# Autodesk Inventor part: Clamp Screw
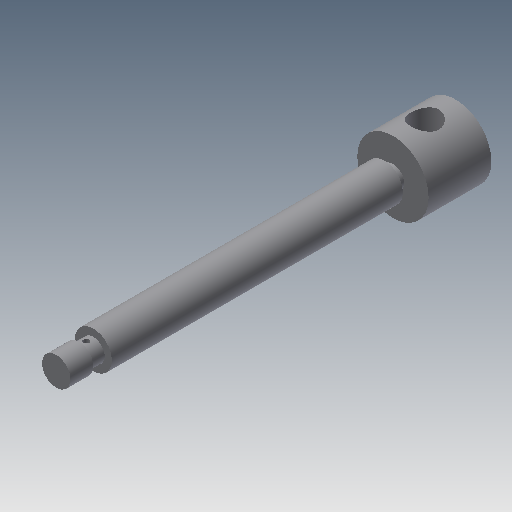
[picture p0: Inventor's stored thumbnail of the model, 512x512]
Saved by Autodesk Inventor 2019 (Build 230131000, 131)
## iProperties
Shininess: 77.0
Length Units: 11269
Angle Units: 11279
Time Units: 11290
Mass Units: 11283
Length Display Precision: 3
Angle Display Precision: 2
Created: 2002-02
Part Number: Clamp Screw
Document SubType Name: Modeling
Designer: ***
Density: 1 g/cm^3
Material: Generic
Mass: 23.4191 g
Surface Area: 81.8482 cm^2
Volume: 23.4191 cm^3
Appearance: Default
Density: 0.0
Volumn: 0.0
Area: 0.0
PropertySet Name: Model Information
Control State: 0
Master: False
Checked Out: False
Author: ***
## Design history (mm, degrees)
sketch "Sketch1"
  geometry: L1 (0, 140)-(5, 140); L2 (5, 140)-(5, 132); L3 (5, 132)-(4, 132); L4 (4, 132)-(4, 127); L5 (4, 127)-(6.5, 127); L6 (6.5, 127)-(6.5, 25); L7 (6.5, 25)-(4, 25); L8 (4, 25)-(4, 22); L9 (4, 22)-(12.5, 22); L10 (12.5, 22)-(12.5, 0); L11 (12.5, 0)-(0, 0); L12 (0, 0)-(0, 140)
  constraints: 24 end point, 10 parallel, 1 horizontal, 1 perpendicular
  dimensions: "d0" = 10 diameter of L2 L12; "d1" = 8 diameter of L4 L12; "d2" = 13 diameter of L6 L12; "d3" = 8 diameter of L7.end L12; "d4" = 25 diameter of L10 L12; "d5" = 3 distance from line of L7.end L9; "d6" = 8 distance of L1.end L2.end; "d7" = 13 vertical distance of L1.end L5.end; "d8" = 22 distance of L9.end L10.end; "d10" = 102 distance of L5.end L6.end
revolve "Revolution1" sketch "Sketch1" stored, may be unused: angle "d11" = 90 deg
sketch "Sketch3"
  geometry: L1 (-12.5, 0)-(12.5, 0) reference; C1 r 5 at (-0.113, 11)
  constraints: 1 centre point
  dimensions: "d13" = 10 diameter of C1; "d14" = 11 distance from line of L1 C1.centre
extrude "Extrusion1" cut sketch "Sketch3" extent not by distance; stored distance "d15" = 10; taper "d16" = 0 deg
sketch "Sketch4"
  geometry: L1 (0, 138.841)-(0, 0); L2 (-12.5, 0)-(12.5, 0) reference; L3 (-5, 140)-(5, 140) reference; C1 r 1 at (0, 129.5)
  constraints: 2 end point, 1 centre point, 1 point on line, 1 vertical
  dimensions: "d17" = 2 diameter of C1; "d18" = 10.5 distance from line of L3 C1.centre
extrude "Extrusion2" cut sketch "Sketch4" stored distance "d19" = 10; taper "d20" = 0 deg
body "Solid1"
